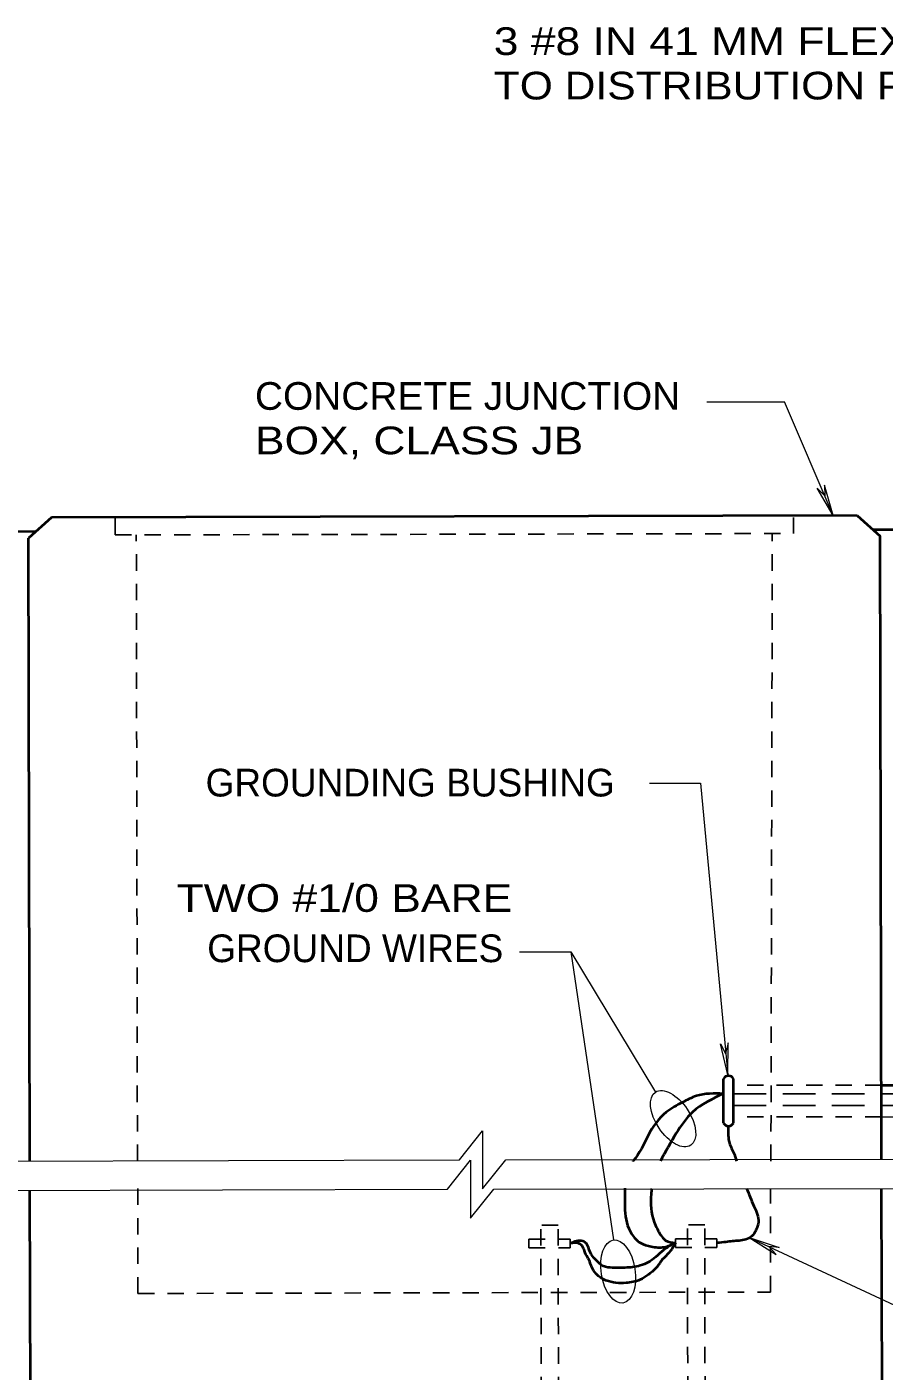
# Model space of a CAD drawing. Extents: x 312583 to 312854, y 144419 to 144597.
# Drawn here: x 312751.27 to 312774.81, y 144448.58 to 144485.47 of the extents above; entities that cross this region are included whole.
import ezdxf

# ---------------------------------------------------------------- set-up
doc = ezdxf.new("R2010")
doc.units = 0
doc.header["$LTSCALE"] = 0.3
doc.linetypes.add('MEDIUM_DASHED', pattern=[4.5, 3, -1.5])
doc.linetypes.add('SHORT_DASHED', pattern=[2.7, 1.5, -1.2])
doc.layers.add('1', color=7, linetype='Continuous', lineweight=40)
doc.layers.add('2', color=7, linetype='Continuous', lineweight=13)

msp = doc.modelspace()

# ---------------------------------------------------------------- linework, layer by layer
at = {"layer": '1'}
for p, q in [((312751.9475, 144472.0036), (312751.3188, 144471.4439)), ((312774.0735, 144472.0572), (312751.9475, 144472.0036)), ((312774.0735, 144472.0572), (312774.7022, 144471.4976)), ((312751.5105, 144471.6202), (312745.5688, 144471.6049)), ((312787.4365, 144471.6969), (312774.5105, 144471.6662)), ((312751.3572, 144454.3472), (312751.3188, 144471.4439)), ((312774.7405, 144454.4009), (312774.7022, 144471.4976)), ((312770.4012, 144455.3899), (312770.4012, 144456.6012)), ((312770.6772, 144455.3899), (312770.6772, 144456.6012)), ((312774.7405, 144456.4326), (312787.4825, 144456.4326)), ((312770.5315, 144455.3056), (312770.5315, 144455.1139)), ((312751.3725, 144447.9456), (312751.3572, 144453.5422)), ((312774.7558, 144447.9992), (312774.7405, 144453.5959))]:
    msp.add_line(p, q, dxfattribs=at)
at = {"layer": '1', "linetype": 'SHORT_DASHED', "lineweight": 25}
for p, q in [((312753.6955, 144471.5282), (312753.6955, 144472.0036)), ((312772.3255, 144471.5666), (312772.3255, 144472.0036)), ((312753.6955, 144471.5282), (312772.3255, 144471.5666)), ((312754.3088, 144454.3472), (312754.2782, 144471.5282)), ((312771.7045, 144454.3472), (312771.7428, 144471.5666)), ((312774.7405, 144456.4326), (312770.6772, 144456.4326)), ((312774.7405, 144455.5586), (312770.6772, 144455.5586)), ((312754.3242, 144450.7132), (312754.3165, 144453.5959)), ((312771.6968, 144450.7516), (312771.6968, 144453.5959)), ((312765.3948, 144447.9762), (312765.3872, 144452.5839)), ((312769.4198, 144447.9916), (312769.4122, 144452.5992)), ((312765.0575, 144452.2006), (312766.1922, 144452.2006)), ((312765.0575, 144451.9629), (312765.0575, 144452.2006)), ((312769.0825, 144452.2159), (312770.2172, 144452.2159)), ((312769.0825, 144451.9782), (312769.0825, 144452.2159)), ((312754.3242, 144450.7132), (312771.6968, 144450.7516))]:
    msp.add_line(p, q, dxfattribs=at)
at = {"layer": '1', "linetype": 'MEDIUM_DASHED', "lineweight": 25}
for p, q in [((312770.6772, 144456.1949), (312789.8438, 144456.1949)), ((312770.6772, 144455.8729), (312789.8592, 144455.8729))]:
    msp.add_line(p, q, dxfattribs=at)
at = {"layer": '1', "lineweight": 13}
msp.add_line((312774.7405, 144455.5586), (312787.4825, 144455.5586), dxfattribs=at)
at = {"layer": '1', "linetype": 'SHORT_DASHED', "lineweight": 25}
for points in [[(312765.8702, 144447.9762), (312765.8625, 144452.5839), (312765.3872, 144452.5839)], [(312769.8952, 144447.9916), (312769.8875, 144452.5992), (312769.4122, 144452.5992)], [(312765.0575, 144451.9629), (312766.1922, 144451.9629), (312766.1922, 144452.2006)], [(312769.0825, 144451.9782), (312770.2172, 144451.9782), (312770.2172, 144452.2159)]]:
    msp.add_lwpolyline(points, dxfattribs=at)
at = {"layer": '1'}
for centre, start, end in [((312770.5392, 144456.5305), 27.14087, 152.85913), ((312770.5392, 144455.4606), 207.14087, 332.85913)]:
    msp.add_arc(centre, 0.1551, start, end, dxfattribs=at)
for points in [[(312770.4012, 144456.1949), (312769.6575, 144456.1336), (312769.2742, 144455.9572), (312768.8295, 144455.6889), (312768.3312, 144455.0526), (312767.9172, 144454.3549), (312767.9095, 144454.3472)], [(312770.4012, 144456.1949), (312769.5502, 144455.6889), (312769.1055, 144455.1139), (312768.6685, 144454.3472)], [(312770.5315, 144455.1139), (312770.5545, 144454.8762), (312770.6772, 144454.5849), (312770.7615, 144454.3472)], [(312767.6948, 144453.6036), (312767.6948, 144453.5959), (312767.6948, 144452.9979), (312767.8788, 144452.3462), (312768.1242, 144452.1009), (312768.4155, 144452.0012), (312768.7758, 144451.9859), (312769.0825, 144452.1009)], [(312768.4308, 144453.5959), (312768.4155, 144453.4426), (312768.4998, 144452.6682), (312768.6762, 144452.3232), (312768.8142, 144452.1699), (312769.0825, 144452.1009)], [(312771.0375, 144453.5959), (312771.2368, 144453.1129), (312771.3595, 144452.6682), (312771.2905, 144452.4536), (312771.1832, 144452.2849), (312771.0145, 144452.1929), (312770.6465, 144452.1469), (312770.4702, 144452.1239), (312770.2172, 144452.1009)], [(312769.0825, 144452.1009), (312768.7528, 144451.9016), (312768.5382, 144451.7099), (312768.1165, 144451.4799), (312767.6948, 144451.4186), (312767.3575, 144451.4186), (312767.1045, 144451.4646), (312766.8898, 144451.6409), (312766.7365, 144451.8479), (312766.6368, 144452.0856), (312766.5372, 144452.1469), (312766.1922, 144452.0856)], [(312769.0825, 144452.1009), (312768.9138, 144451.8402), (312768.7222, 144451.6409), (312768.5382, 144451.3956), (312768.3312, 144451.2269), (312768.1088, 144451.0889), (312767.7255, 144451.0046), (312767.4495, 144451.0046), (312767.1735, 144451.0736), (312766.9742, 144451.1886), (312766.8362, 144451.3419), (312766.7595, 144451.5029), (312766.6905, 144451.6716), (312766.6062, 144451.8249), (312766.5602, 144451.9476), (312766.4682, 144452.0702), (312766.1922, 144452.0856)]]:
    msp.add_spline(points, degree=3, dxfattribs=at)
at = {"layer": '2'}
for p, q in [((312769.9412, 144475.1776), (312772.0802, 144475.1852)), ((312773.4142, 144472.0572), (312772.0802, 144475.1852)), ((312772.9772, 144472.8086), (312773.1842, 144472.6016)), ((312773.4142, 144472.0572), (312772.9772, 144472.8086)), ((312773.1765, 144472.8929), (312773.1842, 144472.6016)), ((312773.4142, 144472.0572), (312773.1765, 144472.8929)), ((312768.3695, 144464.7202), (312769.7725, 144464.7202)), ((312769.7725, 144464.7202), (312770.5238, 144456.7162)), ((312766.2075, 144460.0896), (312767.3805, 144452.1852)), ((312770.3168, 144457.5672), (312770.4548, 144457.2989)), ((312770.5238, 144456.7162), (312770.3168, 144457.5672)), ((312770.5315, 144457.5902), (312770.4548, 144457.2989)), ((312770.5238, 144456.7162), (312770.5315, 144457.5902)), ((312750.2992, 144454.3472), (312763.1485, 144454.3779)), ((312764.4288, 144454.3779), (312775.8828, 144454.4009)), ((312750.2992, 144453.5422), (312762.8188, 144453.5729)), ((312764.0992, 144453.5729), (312775.8828, 144453.5959)), ((312771.1065, 144452.2466), (312777.3932, 144449.3256)), ((312771.1065, 144452.2466), (312771.8502, 144451.7866)), ((312771.1065, 144452.2466), (312771.9345, 144451.9782)), ((312771.8502, 144451.7866), (312771.6432, 144452.0012)), ((312771.9345, 144451.9782), (312771.6432, 144452.0012))]:
    msp.add_line(p, q, dxfattribs=at)
for points in [[(312764.8045, 144460.0896), (312766.2075, 144460.0896), (312768.5305, 144456.2409)], [(312763.1485, 144454.3779), (312763.7848, 144455.1752), (312763.7848, 144453.5806), (312764.4288, 144454.3779)], [(312762.8188, 144453.5729), (312763.4552, 144454.3702), (312763.4552, 144452.7756), (312764.0992, 144453.5729)]]:
    msp.add_lwpolyline(points, dxfattribs=at)
for centre, major_axis in [((312769.0195, 144455.5093), (-0.4859, 0.7295)), ((312767.5104, 144451.3164), (0.1321, -0.8665))]:
    msp.add_ellipse(centre, major_axis=major_axis, ratio=0.53207, dxfattribs=at)

# ---------------------------------------------------------------- texts
for s, width, p in [('3 #8 IN 41 MM FLEXIBLE CONDUIT', 1.2, (312764.0939, 144484.6986)), ('TO DISTRIBUTION PANEL', 1.15, (312764.0939, 144483.4786)), ('CONCRETE JUNCTION', 1.05, (312757.5356, 144474.9619)), ('BOX, CLASS JB', 1.2, (312757.5356, 144473.7419)), ('TWO #1/0 BARE', 1.2, (312755.384, 144461.1849))]:
    msp.add_text(s, height=0.76, dxfattribs=dict(at, width=width)).set_placement(p)
for s, p in [('GROUNDING BUSHING', (312756.1799, 144464.3512)), ('GROUND WIRES', (312756.2248, 144459.8049))]:
    msp.add_text(s, height=0.76, dxfattribs=at).set_placement(p)

doc.saveas('drawing.dxf')
